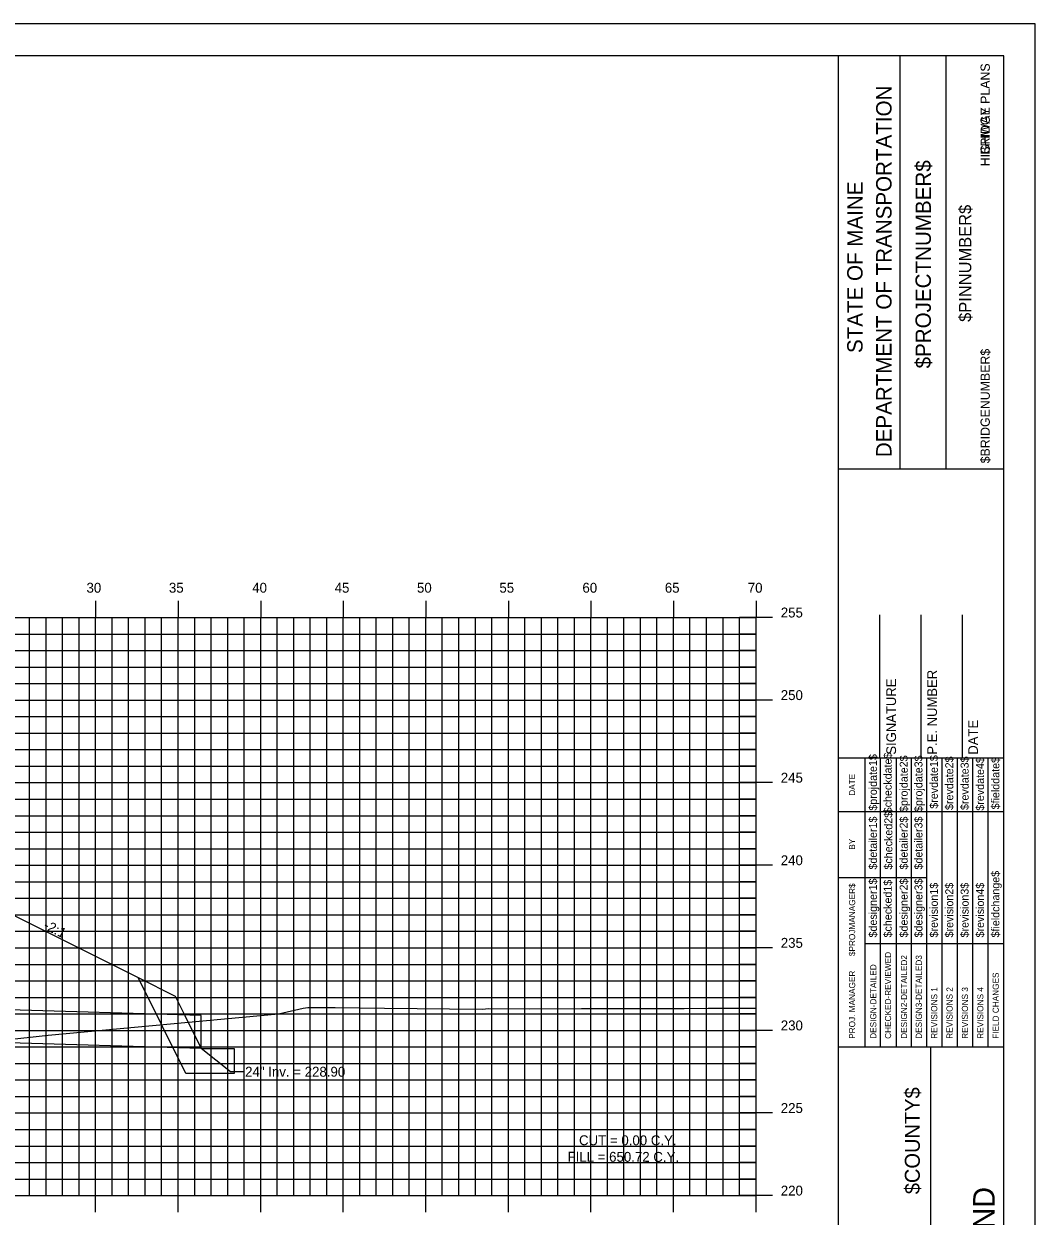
# Model space of a CAD drawing. Extents: x 1160718 to 1173142, y 616002 to 617630.
# Drawn here: x 1169322.8 to 1169384, y 616651.7 to 616723.9 of the extents above; entities that cross this region are included whole.
import ezdxf

# ---------------------------------------------------------------- set-up
doc = ezdxf.new("R2010")
doc.units = 0
for name, color, linetype in [('ANNOTATION', 7, 'Continuous'), ('BORDER', 7, 'Continuous'), ('BRIDGE_TITLE', 7, 'Continuous'), ('D_Drainage_Culvert', 7, 'Continuous'), ('D_Roadway_Centerline', 7, 'Continuous'), ('D_Roadway_Centerline_Text', 7, 'Continuous'), ('H_V ANNOTATION', 7, 'Continuous'), ('HIGHWAY_TITLE', 7, 'Continuous'), ('MAJOR', 7, 'Continuous'), ('MINOR', 7, 'Continuous'), ('PATTERNING', 7, 'Continuous'), ('PLOT BOUNDARY', 7, 'Continuous'), ('S_Roadway_Centerline', 7, 'Continuous')]:
    doc.layers.add(name, color=color, linetype=linetype)

msp = doc.modelspace()

# ---------------------------------------------------------------- linework, layer by layer
at = {"layer": 'ANNOTATION'}
msp.add_line((1169335.524, 616661.828), (1169335.524, 616660.328), dxfattribs=at)
at = {"layer": 'BORDER'}
for p, q in [((1169382.125, 616721.928), (1169222.125, 616721.928)), ((1169372.125, 616616.931), (1169372.125, 616721.931)), ((1169375.853, 616696.925), (1169375.853, 616721.925)), ((1169378.648, 616696.925), (1169378.648, 616721.925)), ((1169382.125, 616616.931), (1169382.125, 616721.931)), ((1169372.125, 616696.923), (1169382.125, 616696.923)), ((1169374.625, 616679.431), (1169374.625, 616688.079)), ((1169377.125, 616679.431), (1169377.125, 616688.079)), ((1169379.625, 616679.431), (1169379.625, 616688.079)), ((1169372.125, 616679.431), (1169382.125, 616679.431)), ((1169372.125, 616661.931), (1169382.125, 616661.931)), ((1169377.716, 616626.931), (1169377.716, 616661.931))]:
    msp.add_line(p, q, dxfattribs=at)
for points in [[(1169373.739, 616676.181), (1169373.739, 616679.431)], [(1169374.672, 616661.934), (1169374.672, 616679.431)], [(1169375.604, 616679.431), (1169375.604, 616661.934)], [(1169376.535, 616661.934), (1169376.535, 616679.431)], [(1169377.467, 616661.934), (1169377.467, 616679.431)], [(1169378.399, 616661.934), (1169378.399, 616679.431)], [(1169379.33, 616661.934), (1169379.33, 616679.431)], [(1169380.262, 616661.934), (1169380.262, 616679.431)], [(1169381.194, 616661.934), (1169381.194, 616679.431)], [(1169373.74, 616661.934), (1169373.74, 616678.725)], [(1169372.125, 616676.181), (1169382.125, 616676.181)], [(1169372.125, 616672.181), (1169373.74, 616672.181)], [(1169373.739, 616672.181), (1169377.466, 616672.181)], [(1169373.739, 616668.181), (1169382.125, 616668.181)]]:
    msp.add_lwpolyline(points, dxfattribs=at)
at = {"layer": 'D_Drainage_Culvert'}
for p, q in [((1169333.524, 616663.828), (1169267.324, 616665.828)), ((1169333.524, 616661.828), (1169267.324, 616663.828)), ((1169333.524, 616661.828), (1169333.524, 616663.828))]:
    msp.add_line(p, q, dxfattribs=at)
at = {"layer": 'D_Roadway_Centerline'}
msp.add_line((1169321.985, 616669.984), (1169329.697, 616666.128), dxfattribs=at)
at = {"layer": 'D_Roadway_Centerline_Text'}
for p, q in [((1169335.292, 616660.415), (1169333.524, 616661.828)), ((1169336.077, 616660.415), (1169335.292, 616660.415))]:
    msp.add_line(p, q, dxfattribs=at)
at = {"layer": 'MAJOR'}
for p, q in [((1169327.124, 616688.93), (1169327.124, 616687.928)), ((1169332.124, 616688.93), (1169332.124, 616687.928)), ((1169337.124, 616688.93), (1169337.124, 616687.928)), ((1169342.124, 616688.93), (1169342.124, 616687.928)), ((1169347.124, 616688.93), (1169347.124, 616687.928)), ((1169352.124, 616688.93), (1169352.124, 616687.928)), ((1169357.124, 616688.93), (1169357.124, 616687.928)), ((1169362.124, 616688.93), (1169362.124, 616687.928)), ((1169367.124, 616688.93), (1169367.124, 616687.928)), ((1169227.124, 616687.928), (1169367.124, 616687.928)), ((1169227.124, 616687.928), (1169367.124, 616687.928)), ((1169327.124, 616652.928), (1169327.124, 616687.928)), ((1169332.124, 616652.928), (1169332.124, 616687.928)), ((1169337.124, 616652.928), (1169337.124, 616687.928)), ((1169342.124, 616652.928), (1169342.124, 616687.928)), ((1169347.124, 616652.928), (1169347.124, 616687.928)), ((1169352.124, 616652.928), (1169352.124, 616687.928)), ((1169357.124, 616652.928), (1169357.124, 616687.928)), ((1169362.124, 616652.928), (1169362.124, 616687.928)), ((1169368.126, 616687.928), (1169366.122, 616687.928)), ((1169367.124, 616652.928), (1169367.124, 616687.928)), ((1169367.124, 616652.928), (1169367.124, 616687.928)), ((1169227.124, 616682.928), (1169367.124, 616682.928)), ((1169368.126, 616682.928), (1169366.122, 616682.928)), ((1169227.124, 616677.928), (1169367.124, 616677.928)), ((1169368.126, 616677.928), (1169366.122, 616677.928)), ((1169227.124, 616672.928), (1169367.124, 616672.928)), ((1169368.126, 616672.928), (1169366.122, 616672.928)), ((1169227.124, 616667.928), (1169367.124, 616667.928)), ((1169368.126, 616667.928), (1169366.122, 616667.928)), ((1169227.124, 616662.928), (1169367.124, 616662.928)), ((1169368.126, 616662.928), (1169366.122, 616662.928)), ((1169227.124, 616657.928), (1169367.124, 616657.928)), ((1169368.126, 616657.928), (1169366.122, 616657.928)), ((1169227.124, 616652.928), (1169367.124, 616652.928)), ((1169227.124, 616652.928), (1169367.124, 616652.928)), ((1169327.124, 616651.926), (1169327.124, 616652.928)), ((1169332.124, 616651.926), (1169332.124, 616652.928)), ((1169337.124, 616651.926), (1169337.124, 616652.928)), ((1169342.124, 616651.926), (1169342.124, 616652.928)), ((1169347.124, 616651.926), (1169347.124, 616652.928)), ((1169352.124, 616651.926), (1169352.124, 616652.928)), ((1169357.124, 616651.926), (1169357.124, 616652.928)), ((1169362.124, 616651.926), (1169362.124, 616652.928)), ((1169368.126, 616652.928), (1169366.122, 616652.928)), ((1169367.124, 616651.926), (1169367.124, 616652.928))]:
    msp.add_line(p, q, dxfattribs=at)
at = {"layer": 'MINOR'}
for p, q in [((1169323.124, 616652.928), (1169323.124, 616687.928)), ((1169324.124, 616652.928), (1169324.124, 616687.928)), ((1169325.124, 616652.928), (1169325.124, 616687.928)), ((1169326.124, 616652.928), (1169326.124, 616687.928)), ((1169328.124, 616652.928), (1169328.124, 616687.928)), ((1169329.124, 616652.928), (1169329.124, 616687.928)), ((1169330.124, 616652.928), (1169330.124, 616687.928)), ((1169331.124, 616652.928), (1169331.124, 616687.928)), ((1169333.124, 616652.928), (1169333.124, 616687.928)), ((1169334.124, 616652.928), (1169334.124, 616687.928)), ((1169335.124, 616652.928), (1169335.124, 616687.928)), ((1169336.124, 616652.928), (1169336.124, 616687.928)), ((1169338.124, 616652.928), (1169338.124, 616687.928)), ((1169339.124, 616652.928), (1169339.124, 616687.928)), ((1169340.124, 616652.928), (1169340.124, 616687.928)), ((1169341.124, 616652.928), (1169341.124, 616687.928)), ((1169343.124, 616652.928), (1169343.124, 616687.928)), ((1169344.124, 616652.928), (1169344.124, 616687.928)), ((1169345.124, 616652.928), (1169345.124, 616687.928)), ((1169346.124, 616652.928), (1169346.124, 616687.928)), ((1169348.124, 616652.928), (1169348.124, 616687.928)), ((1169349.124, 616652.928), (1169349.124, 616687.928)), ((1169350.124, 616652.928), (1169350.124, 616687.928)), ((1169351.124, 616652.928), (1169351.124, 616687.928)), ((1169353.124, 616652.928), (1169353.124, 616687.928)), ((1169354.124, 616652.928), (1169354.124, 616687.928)), ((1169355.124, 616652.928), (1169355.124, 616687.928)), ((1169356.124, 616652.928), (1169356.124, 616687.928)), ((1169358.124, 616652.928), (1169358.124, 616687.928)), ((1169359.124, 616652.928), (1169359.124, 616687.928)), ((1169360.124, 616652.928), (1169360.124, 616687.928)), ((1169361.124, 616652.928), (1169361.124, 616687.928)), ((1169363.124, 616652.928), (1169363.124, 616687.928)), ((1169364.124, 616652.928), (1169364.124, 616687.928)), ((1169365.124, 616652.928), (1169365.124, 616687.928)), ((1169366.124, 616652.928), (1169366.124, 616687.928)), ((1169227.124, 616686.928), (1169367.124, 616686.928)), ((1169367.124, 616686.928), (1169366.122, 616686.928)), ((1169227.124, 616685.928), (1169367.124, 616685.928)), ((1169367.124, 616685.928), (1169366.122, 616685.928)), ((1169227.124, 616684.928), (1169367.124, 616684.928)), ((1169367.124, 616684.928), (1169366.122, 616684.928)), ((1169227.124, 616683.928), (1169367.124, 616683.928)), ((1169367.124, 616683.928), (1169366.122, 616683.928)), ((1169227.124, 616681.928), (1169367.124, 616681.928)), ((1169367.124, 616681.928), (1169366.122, 616681.928)), ((1169227.124, 616680.928), (1169367.124, 616680.928)), ((1169367.124, 616680.928), (1169366.122, 616680.928)), ((1169227.124, 616679.928), (1169367.124, 616679.928)), ((1169367.124, 616679.928), (1169366.122, 616679.928)), ((1169227.124, 616678.928), (1169367.124, 616678.928)), ((1169367.124, 616678.928), (1169366.122, 616678.928)), ((1169227.124, 616676.928), (1169367.124, 616676.928)), ((1169367.124, 616676.928), (1169366.122, 616676.928)), ((1169227.124, 616675.928), (1169367.124, 616675.928)), ((1169367.124, 616675.928), (1169366.122, 616675.928)), ((1169227.124, 616674.928), (1169367.124, 616674.928)), ((1169367.124, 616674.928), (1169366.122, 616674.928)), ((1169227.124, 616673.928), (1169367.124, 616673.928)), ((1169367.124, 616673.928), (1169366.122, 616673.928)), ((1169227.124, 616671.928), (1169367.124, 616671.928)), ((1169367.124, 616671.928), (1169366.122, 616671.928)), ((1169227.124, 616670.928), (1169367.124, 616670.928)), ((1169367.124, 616670.928), (1169366.122, 616670.928)), ((1169227.124, 616669.928), (1169367.124, 616669.928)), ((1169367.124, 616669.928), (1169366.122, 616669.928)), ((1169227.124, 616668.928), (1169367.124, 616668.928)), ((1169367.124, 616668.928), (1169366.122, 616668.928)), ((1169227.124, 616666.928), (1169367.124, 616666.928)), ((1169367.124, 616666.928), (1169366.122, 616666.928)), ((1169227.124, 616665.928), (1169367.124, 616665.928)), ((1169367.124, 616665.928), (1169366.122, 616665.928)), ((1169227.124, 616664.928), (1169367.124, 616664.928)), ((1169367.124, 616664.928), (1169366.122, 616664.928)), ((1169227.124, 616663.928), (1169367.124, 616663.928)), ((1169367.124, 616663.928), (1169366.122, 616663.928)), ((1169227.124, 616661.928), (1169367.124, 616661.928)), ((1169367.124, 616661.928), (1169366.122, 616661.928)), ((1169227.124, 616660.928), (1169367.124, 616660.928)), ((1169367.124, 616660.928), (1169366.122, 616660.928)), ((1169227.124, 616659.928), (1169367.124, 616659.928)), ((1169367.124, 616659.928), (1169366.122, 616659.928)), ((1169227.124, 616658.928), (1169367.124, 616658.928)), ((1169367.124, 616658.928), (1169366.122, 616658.928)), ((1169227.124, 616656.928), (1169367.124, 616656.928)), ((1169367.124, 616656.928), (1169366.122, 616656.928)), ((1169227.124, 616655.928), (1169367.124, 616655.928)), ((1169367.124, 616655.928), (1169366.122, 616655.928)), ((1169227.124, 616654.928), (1169367.124, 616654.928)), ((1169367.124, 616654.928), (1169366.122, 616654.928)), ((1169227.124, 616653.928), (1169367.124, 616653.928)), ((1169367.124, 616653.928), (1169366.122, 616653.928))]:
    msp.add_line(p, q, dxfattribs=at)
at = {"layer": 'PATTERNING'}
msp.add_line((1169332.597, 616660.328), (1169329.697, 616666.128), dxfattribs=at)
for points in [[(1169329.697, 616666.128), (1169331.933, 616665.01)], [(1169331.933, 616665.01), (1169332.524, 616663.828), (1169333.524, 616661.828)], [(1169333.524, 616661.828), (1169335.524, 616661.828)], [(1169335.524, 616660.328), (1169332.597, 616660.328)]]:
    msp.add_lwpolyline(points, dxfattribs=at)
at = {"layer": 'PLOT BOUNDARY'}
msp.add_lwpolyline([(1169214.031, 616613.869), (1169384.031, 616613.869), (1169384.031, 616723.869), (1169214.031, 616723.869)], close=True, dxfattribs=at)
at = {"layer": 'S_Roadway_Centerline'}
msp.add_lwpolyline([(1169318.553, 616662.02), (1169324.252, 616662.636), (1169338.205, 616663.93), (1169339.703, 616664.278), (1169339.979, 616664.318), (1169340.675, 616664.318), (1169341.643, 616664.309), (1169344.631, 616664.279), (1169350.536, 616664.21), (1169350.935, 616664.254), (1169353.433, 616664.237), (1169356.555, 616664.252), (1169358.027, 616664.254), (1169358.281, 616664.254), (1169360.385, 616664.259), (1169361.073, 616664.26), (1169362.763, 616664.264), (1169364.229, 616664.268), (1169365.142, 616664.269), (1169367.124, 616664.271)], dxfattribs=at)

# ---------------------------------------------------------------- texts
at = {"layer": 'ANNOTATION'}
for s, rotation, p in [('-2:1', 333.43495, (1169323.919, 616669.11)), ('CUT = 0.00 C.Y.', 359.92408, (1169356.404, 616655.978)), ('FILL = 650.72 C.Y.', 359.92408, (1169355.707, 616654.977))]:
    msp.add_text(s, height=0.6, rotation=rotation, dxfattribs=at).set_placement(p)
at = {"layer": 'BORDER'}
for s, height, p in [('DEPARTMENT OF TRANSPORTATION', 0.93176, (1169375.331, 616697.634)), ('$PROJECTNUMBER$', 0.93176, (1169377.716, 616703.008)), ('STATE OF MAINE', 0.93176, (1169373.58, 616703.94)), ('$PINNUMBER$', 0.74527, (1169380.161, 616705.825)), ('P.E. NUMBER', 0.59055, (1169378.085, 616679.624)), ('SIGNATURE', 0.5906, (1169375.605, 616679.624)), ('DATE', 0.5906, (1169380.566, 616679.624)), ('$projdate1$', 0.48455, (1169374.447, 616676.232)), ('$checkdate$', 0.48455, (1169375.342, 616676.074)), ('$projdate2$', 0.48455, (1169376.311, 616676.153)), ('$projdate3$', 0.48455, (1169377.205, 616676.153)), ('$revdate1$', 0.4845, (1169378.137, 616676.35)), ('$revdate2$', 0.4845, (1169379.069, 616676.271)), ('$revdate3$', 0.4845, (1169380, 616676.271)), ('$revdate4$', 0.4845, (1169380.932, 616676.232)), ('$fielddate$', 0.48455, (1169381.864, 616676.31)), ('DATE', 0.3714, (1169373.129, 616677.137)), ('$checked2$', 0.4845, (1169375.379, 616672.667)), ('$detailer1$', 0.48455, (1169374.447, 616672.667)), ('$detailer2$', 0.48455, (1169376.311, 616672.667)), ('$detailer3$', 0.48455, (1169377.205, 616672.667)), ('BY', 0.3714, (1169373.129, 616673.866)), ('$fieldchange$', 0.48455, (1169381.864, 616668.555)), ('$PROJMANAGER$', 0.37275, (1169373.129, 616667.426)), ('$designer1$', 0.48455, (1169374.447, 616668.555)), ('$checked1$', 0.4845, (1169375.342, 616668.555)), ('$designer2$', 0.48455, (1169376.311, 616668.555)), ('$designer3$', 0.48455, (1169377.205, 616668.555)), ('$revision1$', 0.48455, (1169378.137, 616668.555)), ('$revision2$', 0.48455, (1169379.069, 616668.555)), ('$revision3$', 0.48455, (1169380, 616668.555)), ('$revision4$', 0.48455, (1169380.932, 616668.555)), ('CHECKED-REVIEWED', 0.37275, (1169375.306, 616662.419)), ('DESIGN2-DETAILED2', 0.37275, (1169376.274, 616662.419)), ('DESIGN3-DETAILED3', 0.37275, (1169377.169, 616662.419)), ('PROJ. MANAGER', 0.37275, (1169373.129, 616662.419)), ('DESIGN-DETAILED', 0.37275, (1169374.411, 616662.419)), ('FIELD CHANGES', 0.37275, (1169381.827, 616662.419)), ('REVISIONS 1', 0.37275, (1169378.101, 616662.419)), ('REVISIONS 2', 0.37275, (1169379.032, 616662.419)), ('REVISIONS 3', 0.37275, (1169379.964, 616662.419)), ('REVISIONS 4', 0.37275, (1169380.896, 616662.419)), ('DIVERSION I-95 NORTHBOUND  ', 1.30428, (1169381.578, 616627.379))]:
    msp.add_text(s, height=height, rotation=90, dxfattribs=at).set_placement(p)
at = {"layer": 'BRIDGE_TITLE'}
for s, height, p in [('BRIDGE PLANS', 0.55901, (1169381.283, 616715.953)), ('$BRIDGENUMBER$', 0.55901, (1169381.283, 616697.259)), ('$COUNTY$', 0.9072, (1169377.045, 616653.011))]:
    msp.add_text(s, height=height, rotation=90, dxfattribs=at).set_placement(p)
at = {"layer": 'D_Roadway_Centerline_Text'}
msp.add_text('24" Inv. = 228.90', height=0.6, dxfattribs=at).set_placement((1169336.18, 616660.125))
at = {"layer": 'H_V ANNOTATION'}
for s, p in [('30', (1169326.573, 616689.428)), ('35', (1169331.565, 616689.428)), ('40', (1169336.61, 616689.428)), ('45', (1169341.602, 616689.428)), ('50', (1169346.589, 616689.428)), ('55', (1169351.581, 616689.428)), ('60', (1169356.61, 616689.428)), ('65', (1169361.602, 616689.428)), ('70', (1169366.626, 616689.428)), ('255', (1169368.624, 616687.928)), ('250', (1169368.624, 616682.928)), ('245', (1169368.624, 616677.928)), ('240', (1169368.624, 616672.928)), ('235', (1169368.624, 616667.928)), ('230', (1169368.624, 616662.928)), ('225', (1169368.624, 616657.928)), ('220', (1169368.624, 616652.928))]:
    msp.add_text(s, height=0.6, dxfattribs=at).set_placement(p)
at = {"layer": 'HIGHWAY_TITLE'}
msp.add_text('HIGHWAY PLANS', height=0.55901, rotation=90, dxfattribs=at).set_placement((1169381.283, 616715.244))

doc.saveas('drawing.dxf')
